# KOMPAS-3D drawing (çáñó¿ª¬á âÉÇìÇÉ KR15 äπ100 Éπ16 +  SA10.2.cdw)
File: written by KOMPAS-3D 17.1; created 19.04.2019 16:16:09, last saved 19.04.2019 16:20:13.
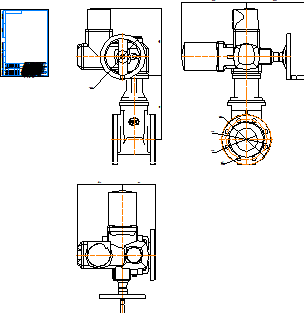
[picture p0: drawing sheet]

Sheet 1: A4, portrait

Title block, sheet 1: name: Задвижка ГРАНАР KR15 Ду100 Ру16 + / SA10.2; material: Внимание! Данный продукт является объектом авторского права ООО «Торговый Дом АДЛ». / Запрещается изменение, копирование, распространение / (в том числе путем копирования на другие сайты и ресурсы в Интернете) / или любое иное использование информации и объектов без предварительного / согласия правообладателя (ООО «Торговый Дом АДЛ»).; mass: 102,11; sheets: 1; organisation: ООО "Торговый дом АДЛ"; sheet format: A4; stored path: \\adlc.lan\data\АДЛ_ПКД\3D-модели\ADL production\Клиновые задвижки серии KR ГРАНАР\Клиновые задвижки KR15\С эл.приводом\KOMPAS 2D\Задвижка ГРАНАР KR15 Ду100 Ру16 +  SA10.2.cdw

Views: Вид 1, Проекционный вид 2, Проекционный вид 3
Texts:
  user
Dimensions and other numbers on the sheet: 282; 290; 200; 220; 180; 100; 19; 8 Отв.; 253,7; 197,8; 145; 1:1; 1; 102,11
